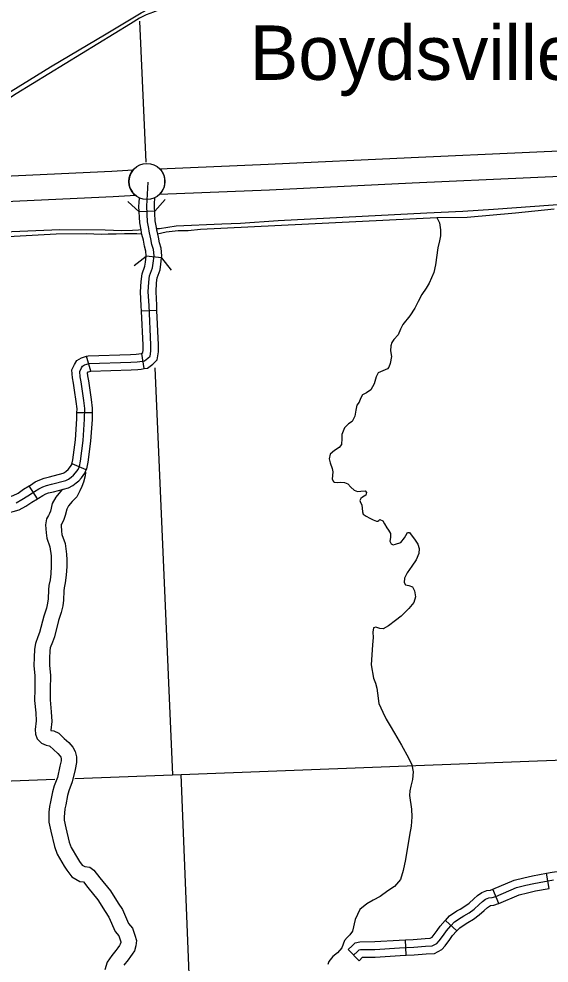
# Model space of a CAD drawing. Extents: x -5566 to 1759129, y -3726 to 731467.
# Drawn here: x -4742.8 to -4703.7, y 261.2 to 330.8 of the extents above; entities that cross this region are included whole.
import ezdxf

# ---------------------------------------------------------------- set-up
doc = ezdxf.new("R2010")
doc.units = 0
doc.layers.add('Default', color=7, linetype='Continuous')

msp = doc.modelspace()

# ---------------------------------------------------------------- linework, layer by layer
at = {"layer": 'Default'}
for p, q in [((-4732.775, 316.665), (-4733.913, 316.602)), ((-4732.271, 313.21), (-4733.403, 313.343)), ((-4732.61, 309.342), (-4733.748, 309.293)), ((-4737.488, 304.864), (-4737.811, 305.957)), ((-4733.562, 305.045), (-4733.735, 306.171)), ((-4737.366, 301.781), (-4738.505, 301.79)), ((-4737.824, 297.572), (-4738.865, 298.035)), ((-4741.422, 295.441), (-4742.027, 296.406)), ((-4703.718, 266.709), (-4703.919, 267.831)), ((-4707.425, 265.604), (-4707.865, 266.655)), ((-4710.528, 263.578), (-4711.36, 264.356)), ((-4714.242, 261.788), (-4714.299, 262.926)), ((-4717.725, 261.382), (-4718.512, 262.206))]:
    msp.add_line(p, q, dxfattribs=at)
for points in [[(-4696.252, 355.061), (-4696.632, 354.686), (-4697.139, 354.156), (-4698.831, 353.208), (-4705.395, 349.146), (-4717.477, 341.348), (-4731.156, 332.251), (-4732.102, 331.642), (-4732.867, 331.328), (-4733.4, 331.136), (-4733.902, 330.892), (-4734.572, 330.459), (-4742.996, 325.302), (-4744.672, 324.236), (-4746.615, 322.956), (-4748.105, 322.025), (-4751.473, 319.9), (-4753.098, 318.821)], [(-4754.128, 318.759), (-4750.752, 320.921), (-4747.973, 322.677), (-4744.417, 324.862), (-4740.467, 327.31), (-4736.357, 329.733), (-4733.777, 331.269), (-4732.753, 331.827), (-4731.996, 332.156), (-4731.432, 332.577), (-4730.561, 333.153)], [(-4733.91, 330.677), (-4733.444, 320.274)], [(-4732.418, 319.787), (-4724.407, 320.109), (-4713.887, 320.622), (-4696.453, 321.408), (-4690.907, 321.664), (-4690.844, 321.2), (-4690.768, 320.72), (-4690.657, 320.175), (-4690.55, 319.78)], [(-4751.821, 318.897), (-4748.112, 319.035), (-4735.949, 319.604), (-4734.369, 319.692), (-4734.52, 319.478), (-4734.628, 319.185), (-4734.685, 318.866), (-4734.649, 318.572), (-4734.577, 318.335), (-4734.448, 318.093), (-4734.335, 317.944), (-4734.179, 317.802)], [(-4690.55, 319.78), (-4696.366, 319.512), (-4713.798, 318.726), (-4724.322, 318.212), (-4732.423, 317.887), (-4732.267, 318.057), (-4732.154, 318.243), (-4732.061, 318.469), (-4732.02, 318.711), (-4732.02, 318.989), (-4732.066, 319.221), (-4732.159, 319.447), (-4732.282, 319.643), (-4732.418, 319.787)], [(-4734.179, 317.802), (-4735.851, 317.708), (-4748.032, 317.139), (-4751.726, 317.001), (-4751.821, 318.897)], [(-4733.187, 315.173), (-4733.214, 315.37), (-4733.302, 315.871), (-4733.365, 317.024), (-4733.265, 318.803)], [(-4733.922, 317.265), (-4733.902, 317.631)], [(-4732.785, 317.201), (-4732.76, 317.649)], [(-4732.015, 317.513), (-4732.775, 316.665)], [(-4733.913, 316.602), (-4734.761, 317.362)], [(-4733.403, 313.343), (-4733.399, 313.372), (-4733.431, 313.711), (-4733.535, 314.062), (-4733.611, 314.505), (-4733.723, 314.94), (-4733.749, 315.082), (-4733.777, 315.281), (-4733.869, 315.806), (-4733.936, 317.024), (-4733.922, 317.265)], [(-4732.271, 313.21), (-4732.254, 313.358), (-4732.307, 313.929), (-4732.424, 314.322), (-4732.496, 314.743), (-4732.609, 315.185), (-4732.624, 315.265), (-4732.651, 315.459), (-4732.735, 315.936), (-4732.795, 317.023), (-4732.785, 317.201)], [(-4732.635, 315.366), (-4732.426, 315.367), (-4731.188, 315.575), (-4727.832, 315.732), (-4726.452, 315.782), (-4723.678, 315.96), (-4712.739, 316.535), (-4710.086, 316.658), (-4707.816, 316.795), (-4702.076, 317.213)], [(-4732.561, 314.995), (-4731.928, 315.131), (-4731.061, 315.226), (-4730.308, 315.234), (-4729.399, 315.331), (-4711.997, 316.194), (-4709.744, 316.221), (-4706.19, 316.527), (-4703.342, 316.824)], [(-4711.997, 316.194), (-4711.795, 315.803), (-4711.759, 315.621), (-4711.726, 315.279), (-4711.728, 314.845), (-4711.8, 314.461), (-4711.906, 313.962), (-4712.08, 312.706), (-4712.207, 312.138), (-4712.547, 311.35), (-4712.779, 310.977), (-4713.099, 310.509), (-4713.364, 309.998), (-4713.6, 309.503), (-4713.992, 308.941), (-4714.505, 308.308), (-4714.676, 307.959), (-4714.838, 307.535), (-4715.162, 307.197), (-4715.314, 306.971), (-4715.375, 306.718), (-4715.409, 306.358), (-4715.336, 305.949), (-4715.418, 305.412), (-4715.532, 305.15), (-4715.627, 305.032), (-4715.964, 304.869), (-4716.301, 304.729), (-4716.459, 304.442), (-4716.618, 303.926), (-4716.855, 303.477), (-4717.182, 303.253), (-4717.467, 303.107), (-4717.618, 302.851), (-4717.716, 302.581), (-4717.884, 302.347), (-4717.971, 301.971), (-4718.041, 301.534), (-4718.219, 301.147), (-4718.502, 300.97), (-4718.789, 300.672), (-4719.002, 300.177), (-4718.986, 299.888), (-4719.01, 299.437), (-4719.178, 299.234), (-4719.528, 299.002), (-4719.854, 298.733), (-4719.935, 298.402), (-4719.85, 298.107), (-4719.693, 297.685), (-4719.662, 297.435), (-4719.714, 296.899), (-4719.595, 296.712), (-4719.525, 296.669), (-4719.319, 296.645), (-4719.054, 296.683), (-4718.788, 296.654), (-4718.549, 296.547), (-4718.321, 296.295), (-4718.079, 296.089), (-4717.826, 295.99), (-4717.583, 296.012), (-4717.28, 296.022), (-4717.17, 295.911), (-4717.21, 295.719), (-4717.471, 295.574), (-4717.582, 295.479), (-4717.676, 295.323), (-4717.626, 295.165), (-4717.522, 294.993), (-4717.461, 294.484), (-4717.425, 294.309), (-4717.208, 294.171), (-4716.938, 294.027), (-4716.69, 293.882), (-4716.437, 293.791), (-4716.338, 293.787), (-4716.271, 293.834), (-4716.183, 293.921), (-4715.975, 293.828), (-4715.839, 293.596), (-4715.685, 293.296), (-4715.543, 293.125), (-4715.407, 292.885), (-4715.413, 292.595), (-4715.443, 292.328), (-4715.345, 292.125), (-4715.206, 292.053), (-4715.033, 292.104), (-4714.642, 292.23), (-4714.364, 292.575), (-4714.278, 292.73), (-4714.141, 292.963), (-4713.996, 292.96), (-4713.813, 292.691), (-4713.632, 292.475), (-4713.385, 292.102), (-4713.292, 291.792), (-4713.326, 291.417), (-4713.525, 290.954), (-4713.829, 290.479)], [(-4746.846, 315.005), (-4739.766, 315.315), (-4736.431, 315.269), (-4735.205, 315.237), (-4734.412, 315.258), (-4733.968, 315.269), (-4733.78, 315.3)], [(-4743.585, 314.785), (-4740.036, 314.979), (-4737.826, 315.015), (-4736.702, 314.96), (-4736.198, 314.994), (-4735.627, 314.994), (-4734.993, 315.004), (-4734.084, 315.004), (-4733.73, 314.98)], [(-4742.988, 295.158), (-4742.557, 295.381), (-4742.134, 295.667), (-4741.635, 295.98), (-4741.311, 296.187), (-4741.022, 296.328), (-4740.76, 296.419), (-4740.375, 296.517), (-4739.328, 296.799), (-4739.12, 296.903), (-4738.925, 297.049), (-4738.772, 297.191), (-4738.612, 297.35), (-4738.429, 297.613), (-4738.331, 297.834), (-4738.251, 298.231), (-4738.058, 299.742), (-4737.94, 301.324), (-4737.933, 302.097), (-4737.994, 302.697), (-4738.129, 303.548), (-4738.197, 304.059), (-4738.276, 304.448), (-4738.3, 304.839), (-4738.184, 305.094), (-4738.105, 305.226), (-4737.948, 305.322), (-4737.602, 305.424), (-4734.539, 305.52), (-4734.082, 305.543), (-4733.866, 305.575), (-4733.535, 305.626), (-4733.291, 305.806), (-4733.122, 305.964), (-4733.066, 306.328), (-4733.07, 306.789), (-4733.196, 309.707), (-4733.249, 310.712), (-4733.217, 311.409), (-4733.154, 311.885), (-4732.943, 312.467), (-4732.89, 312.826), (-4732.826, 313.365), (-4732.869, 313.82), (-4732.98, 314.192), (-4733.054, 314.624), (-4733.166, 315.063), (-4733.187, 315.173)], [(-4734.297, 312.637), (-4733.403, 313.343)], [(-4733.748, 309.293), (-4733.765, 309.68), (-4733.819, 310.709), (-4733.785, 311.46), (-4733.71, 312.022), (-4733.498, 312.607), (-4733.455, 312.901), (-4733.403, 313.343)], [(-4732.61, 309.342), (-4732.627, 309.734), (-4732.679, 310.714), (-4732.65, 311.359), (-4732.598, 311.749), (-4732.388, 312.327), (-4732.325, 312.752), (-4732.271, 313.21)], [(-4732.271, 313.21), (-4731.565, 312.316)], [(-4733.76, 306.167), (-4733.657, 306.244), (-4733.655, 306.246), (-4733.635, 306.37), (-4733.639, 306.774), (-4733.748, 309.293)], [(-4733.562, 305.045), (-4733.309, 305.084), (-4732.926, 305.367), (-4732.59, 305.683), (-4732.496, 306.286), (-4732.5, 306.804), (-4732.61, 309.342)], [(-4738.505, 301.79), (-4738.503, 302.07), (-4738.559, 302.623), (-4738.693, 303.466), (-4738.759, 303.965), (-4738.842, 304.372), (-4738.878, 304.946), (-4738.689, 305.36), (-4738.521, 305.638), (-4738.182, 305.847), (-4737.811, 305.957)], [(-4737.811, 305.957), (-4737.693, 305.991), (-4734.562, 306.089), (-4734.138, 306.11), (-4733.952, 306.138), (-4733.735, 306.171)], [(-4737.511, 304.857), (-4734.516, 304.951), (-4734.025, 304.975), (-4733.781, 305.012), (-4733.562, 305.045)], [(-4732.775, 305.091), (-4731.463, 275.094)], [(-4737.366, 301.781), (-4737.363, 302.124), (-4737.429, 302.77), (-4737.566, 303.629), (-4737.635, 304.153), (-4737.71, 304.523), (-4737.723, 304.733), (-4737.69, 304.804), (-4737.488, 304.864)], [(-4738.877, 298.007), (-4738.814, 298.323), (-4738.625, 299.799), (-4738.509, 301.348), (-4738.505, 301.79)], [(-4737.824, 297.572), (-4737.785, 297.66), (-4737.689, 298.139), (-4737.492, 299.685), (-4737.37, 301.3), (-4737.366, 301.781)], [(-4742.027, 296.406), (-4741.94, 296.461), (-4741.59, 296.684), (-4741.241, 296.855), (-4740.924, 296.965), (-4740.519, 297.068), (-4739.532, 297.334), (-4739.421, 297.39), (-4739.29, 297.488), (-4739.166, 297.602), (-4739.051, 297.717), (-4738.927, 297.894), (-4738.865, 298.035)], [(-4741.422, 295.441), (-4741.331, 295.499), (-4741.032, 295.689), (-4740.802, 295.802), (-4740.596, 295.874), (-4740.231, 295.966), (-4739.125, 296.264), (-4738.82, 296.417), (-4738.56, 296.611), (-4738.377, 296.78), (-4738.174, 296.983), (-4737.931, 297.332), (-4737.824, 297.572)], [(-4737.876, 297.41), (-4737.903, 297.134), (-4738.021, 296.679), (-4738.15, 296.348), (-4738.299, 296.03), (-4738.527, 295.602), (-4738.851, 295.237), (-4739.12, 294.925), (-4739.25, 294.682), (-4739.364, 294.203), (-4739.476, 293.913), (-4739.592, 293.658), (-4739.66, 293.552), (-4739.674, 293.468), (-4739.649, 293.051), (-4739.612, 292.82), (-4739.387, 292.159), (-4739.277, 291.351), (-4739.26, 290.938), (-4739.26, 290.453), (-4739.292, 289.803), (-4739.367, 289.26), (-4739.45, 288.877), (-4739.474, 288.663), (-4739.49, 287.966), (-4739.552, 287.54), (-4739.663, 287.07), (-4739.863, 286.469), (-4740.17, 285.264), (-4740.312, 284.864), (-4740.47, 284.458), (-4740.507, 284.242), (-4740.521, 283.701), (-4740.535, 283.184), (-4740.467, 282.425), (-4740.475, 281.393), (-4740.49, 280.62), (-4740.408, 279.74), (-4740.366, 279.029), (-4740.443, 278.388), (-4740.442, 278.371), (-4740.44, 278.37), (-4740.211, 278.323), (-4739.837, 278.155), (-4739.461, 277.779), (-4739.107, 277.465), (-4738.803, 277.131), (-4738.629, 276.807), (-4738.532, 276.418), (-4738.543, 275.994), (-4738.645, 275.479), (-4738.852, 274.571), (-4739.1, 273.913), (-4739.206, 273.567), (-4739.339, 272.883), (-4739.398, 272.574), (-4739.437, 272.256), (-4739.448, 271.993), (-4739.438, 271.749), (-4739.317, 271.188), (-4739.075, 270.136), (-4738.93, 269.735), (-4738.467, 268.947), (-4738.316, 268.705), (-4738.111, 268.43), (-4737.939, 268.329), (-4737.57, 268.292), (-4737.252, 268.059), (-4736.818, 267.493), (-4736.043, 266.542), (-4735.469, 265.626), (-4735.145, 265.149), (-4734.701, 264.127), (-4734.424, 263.793), (-4734.24, 263.275), (-4734.12, 262.875), (-4734.167, 262.479), (-4734.278, 262.121), (-4734.435, 261.871), (-4734.567, 261.684), (-4734.729, 261.453), (-4735.045, 261.051)], [(-4745.51, 295.464), (-4744.536, 295.496), (-4743.889, 295.518), (-4743.496, 295.601), (-4743.202, 295.689), (-4742.849, 295.872), (-4742.445, 296.144), (-4742.027, 296.406)], [(-4739.568, 296.145), (-4739.708, 295.986), (-4740.063, 295.575), (-4740.324, 295.091), (-4740.455, 294.541), (-4740.527, 294.354), (-4740.595, 294.205), (-4740.747, 293.968), (-4740.819, 293.526), (-4740.783, 292.927), (-4740.721, 292.545), (-4740.501, 291.896), (-4740.412, 291.251), (-4740.399, 290.915), (-4740.399, 290.482), (-4740.427, 289.909), (-4740.49, 289.458), (-4740.575, 289.062), (-4740.612, 288.74), (-4740.627, 288.061), (-4740.672, 287.753), (-4740.76, 287.382), (-4740.957, 286.79), (-4741.261, 285.595), (-4741.38, 285.261), (-4741.573, 284.764), (-4741.643, 284.354), (-4741.66, 283.732), (-4741.676, 283.149), (-4741.607, 282.378), (-4741.614, 281.408), (-4741.63, 280.578), (-4741.544, 279.653), (-4741.509, 279.064), (-4741.585, 278.434), (-4741.572, 278.093), (-4741.433, 277.747), (-4741.122, 277.42), (-4740.778, 277.277), (-4740.563, 277.232), (-4740.494, 277.201), (-4740.243, 276.95), (-4739.909, 276.653), (-4739.74, 276.467), (-4739.7, 276.393), (-4739.675, 276.292), (-4739.679, 276.121), (-4739.76, 275.718), (-4739.946, 274.899), (-4740.179, 274.281), (-4740.313, 273.843), (-4740.457, 273.099), (-4740.524, 272.751), (-4740.574, 272.349), (-4740.588, 271.993), (-4740.573, 271.605), (-4740.429, 270.94), (-4740.169, 269.814), (-4739.966, 269.249), (-4739.442, 268.357), (-4739.258, 268.061), (-4738.886, 267.564), (-4738.3, 267.22), (-4738.023, 267.193), (-4737.712, 266.787), (-4736.971, 265.877), (-4736.423, 265.003), (-4736.147, 264.597), (-4735.681, 263.525), (-4735.43, 263.222), (-4735.323, 262.921), (-4735.279, 262.775), (-4735.286, 262.716), (-4735.322, 262.601), (-4735.383, 262.504), (-4735.499, 262.338), (-4735.644, 262.132), (-4735.937, 261.759), (-4736.283, 261.266), (-4736.464, 260.714)], [(-4745.473, 294.326), (-4744.498, 294.357), (-4743.751, 294.383), (-4743.214, 294.496), (-4742.773, 294.628), (-4742.266, 294.89), (-4741.823, 295.19), (-4741.422, 295.441)], [(-4713.829, 290.479), (-4714.171, 289.981), (-4714.364, 289.601), (-4714.4, 289.272), (-4714.288, 289.108), (-4714.044, 289.047), (-4713.783, 288.963), (-4713.629, 288.663), (-4713.57, 288.207), (-4713.687, 287.807), (-4714.052, 287.354), (-4714.627, 286.779), (-4715.043, 286.461), (-4715.563, 286.079), (-4715.943, 285.861), (-4716.179, 285.869), (-4716.494, 285.982), (-4716.66, 285.938), (-4716.718, 285.601), (-4716.683, 285.228), (-4716.727, 284.686), (-4716.826, 283.196), (-4716.652, 282.218), (-4716.519, 281.841), (-4716.409, 281.47), (-4716.36, 281.114), (-4716.268, 280.354), (-4715.975, 279.7), (-4715.716, 279.189), (-4715.42, 278.695), (-4715.108, 278.171), (-4714.602, 277.272), (-4714.08, 276.35), (-4713.828, 275.817), (-4713.737, 275.316), (-4713.78, 274.736), (-4713.894, 274.244), (-4713.99, 273.913), (-4714.01, 273.577), (-4713.865, 272.567), (-4713.833, 272.004), (-4713.887, 271.293), (-4714.003, 270.634), (-4714.291, 268.856), (-4714.478, 268.034), (-4714.67, 267.365), (-4715.118, 266.848), (-4715.609, 266.528), (-4716.158, 266.114), (-4716.674, 265.839), (-4717.136, 265.565), (-4717.656, 265.149), (-4718.013, 264.414), (-4718.198, 263.571), (-4718.395, 263.282), (-4718.593, 263.097), (-4718.786, 262.876), (-4718.997, 262.328), (-4719.305, 261.968), (-4719.653, 261.705), (-4719.946, 261.33), (-4720.03, 261.106)], [(-4738.666, 274.817), (-4731.463, 275.094), (-4730.826, 275.118), (-4693.037, 276.571)], [(-4729.388, 238.938), (-4730.826, 275.118)], [(-4758.71, 274.047), (-4740.138, 274.76)], [(-4703.919, 267.831), (-4703.493, 267.907), (-4701.69, 268.152), (-4699.924, 268.391)], [(-4707.865, 266.655), (-4706.295, 267.313), (-4705.579, 267.496), (-4704.953, 267.645), (-4703.919, 267.831)], [(-4718.119, 261.794), (-4717.829, 262.07), (-4717.724, 262.176), (-4717.605, 262.202), (-4716.548, 262.221), (-4714.736, 262.334), (-4713.696, 262.386), (-4712.814, 262.452), (-4712.331, 262.473), (-4711.984, 262.663), (-4711.813, 262.847), (-4711.501, 263.277), (-4711.287, 263.585), (-4710.958, 263.953), (-4710.678, 264.252), (-4710.207, 264.572), (-4709.997, 264.691), (-4709.601, 264.924), (-4709.244, 265.195), (-4708.878, 265.52), (-4708.628, 265.744), (-4708.404, 265.915), (-4708.167, 266.008), (-4707.917, 266.034), (-4707.653, 266.126), (-4706.113, 266.771), (-4705.442, 266.943), (-4704.836, 267.087), (-4703.404, 267.344)], [(-4707.425, 265.604), (-4705.932, 266.23), (-4705.305, 266.39), (-4704.72, 266.53), (-4703.718, 266.709)], [(-4711.36, 264.356), (-4711.051, 264.688), (-4710.508, 265.057), (-4710.281, 265.184), (-4709.919, 265.398), (-4709.606, 265.635), (-4709.257, 265.946), (-4708.991, 266.183), (-4708.686, 266.417), (-4708.302, 266.566), (-4708.042, 266.593), (-4707.858, 266.658), (-4707.865, 266.655)], [(-4710.528, 263.578), (-4710.305, 263.817), (-4709.907, 264.088), (-4709.712, 264.197), (-4709.283, 264.451), (-4708.883, 264.754), (-4708.499, 265.095), (-4708.264, 265.305), (-4708.122, 265.414), (-4708.031, 265.449), (-4707.791, 265.474), (-4707.449, 265.594), (-4707.424, 265.605)], [(-4714.299, 262.926), (-4713.731, 262.955), (-4712.847, 263.021), (-4712.488, 263.036), (-4712.339, 263.118), (-4712.254, 263.21), (-4711.965, 263.607), (-4711.734, 263.938), (-4711.378, 264.338), (-4711.36, 264.356)], [(-4714.242, 261.788), (-4713.66, 261.818), (-4712.78, 261.883), (-4712.173, 261.91), (-4711.63, 262.208), (-4711.373, 262.485), (-4711.037, 262.947), (-4710.839, 263.231), (-4710.537, 263.569), (-4710.528, 263.578)], [(-4718.512, 262.206), (-4718.227, 262.478), (-4718.009, 262.696), (-4717.673, 262.77), (-4716.571, 262.791), (-4714.768, 262.902), (-4714.299, 262.926)], [(-4717.725, 261.382), (-4717.46, 261.635), (-4716.525, 261.652), (-4714.704, 261.765), (-4714.242, 261.788)]]:
    msp.add_lwpolyline(points, dxfattribs=at)
msp.add_circle((-4733.35, 318.84), 1.329, dxfattribs=at)

# ---------------------------------------------------------------- texts
msp.add_text('Boydsville', height=4.0097, dxfattribs=at).set_placement((-4725.773, 326.338))

doc.saveas('drawing.dxf')
